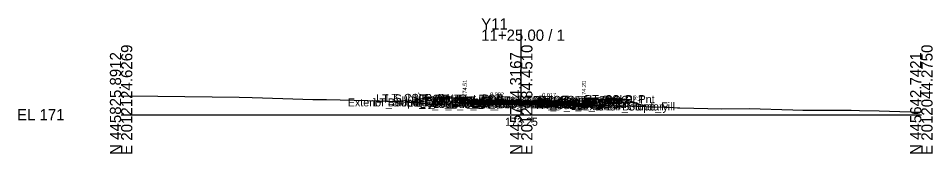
# Model space of a CAD drawing. Extents: x -26 to 203, y -10 to 3517.
# Drawn here: x -25.7 to 202.8, y 2490.3 to 2524 of the extents above; entities that cross this region are included whole.
import ezdxf

# ---------------------------------------------------------------- set-up
doc = ezdxf.new("R2010")
doc.units = 0
for name, color, linetype in [('Default', 7, 'Continuous'), ('Exist Cross Section Cell', 7, 'Continuous'), ('Exist XS Center Line Elevation Label', 7, 'Continuous'), ('Exist XS Ground Line', 7, 'Continuous'), ('Prop CMT Conc Surface', 7, 'Continuous'), ('Prop CMT Concrete Structures', 7, 'Continuous'), ('Prop CMT Pvmt Course 1', 7, 'Continuous'), ('Prop CMT Pvmt Course 1 CG', 7, 'Continuous'), ('Prop CMT Pvmt Course 2', 7, 'Continuous'), ('Prop CMT Pvmt Course 3', 7, 'Continuous'), ('Prop CMT Pvmt Surface', 7, 'Continuous'), ('Prop CMT Slope Grass', 7, 'Continuous'), ('Prop CMT Subgrade Earthwork', 7, 'Continuous'), ('Prop XS Earthwork Shape', 7, 'Continuous'), ('Prop XS Hydro Elevations', 7, 'Continuous'), ('Prop XS SE Text', 7, 'Continuous'), ('Prop XS Side Slope Text', 7, 'Continuous'), ('Scratch_Level_0', 7, 'Continuous')]:
    doc.layers.add(name, color=color, linetype=linetype)

msp = doc.modelspace()

# ---------------------------------------------------------------- linework, layer by layer
at = {"layer": 'Exist Cross Section Cell'}
for p, q in [((100, 2500), (100, 2521.22)), ((0, 2500), (100, 2500)), ((100, 2500), (200, 2500))]:
    msp.add_line(p, q, dxfattribs=at)
at = {"layer": 'Exist XS Ground Line'}
msp.add_lwpolyline([(0, 2504.75), (9.22, 2504.59), (29.53, 2504.38), (32.75, 2504.31), (40.45, 2504.01), (47.93, 2503.83), (51.37, 2503.78), (61.68, 2503.52), (69.29, 2503.3), (73.96, 2502.98), (87.43, 2502.16), (88.96, 2502.1), (91.29, 2502.17), (98.51, 2502.22), (100, 2502.25), (100.43, 2502.25), (108.03, 2502.02), (112.71, 2501.73), (113.1, 2501.82), (113.46, 2502.05), (116.73, 2502.12), (123.62, 2502.21), (128.97, 2502.16), (138.03, 2501.79), (139.02, 2501.76), (139.66, 2501.73), (150.15, 2501.44), (156.98, 2501.55), (167.86, 2501.2), (170.38, 2501.18), (176.95, 2501.13), (182.43, 2501.12), (184.57, 2501.06), (189.45, 2500.96), (194.64, 2500.83), (200, 2500.68)], dxfattribs=at)
at = {"layer": 'Prop CMT Conc Surface'}
for points in [[(85.89, 2503.51), (85.89, 2504.01), (85.39, 2504.01)], [(87.89, 2503.59), (85.89, 2503.51)], [(113.69, 2503.32), (115.69, 2503.2)], [(115.69, 2503.2), (115.69, 2503.7), (116.19, 2503.7)]]:
    msp.add_lwpolyline(points, dxfattribs=at)
at = {"layer": 'Prop CMT Concrete Structures'}
for points in [[(87.89, 2503.59), (85.89, 2503.51), (85.89, 2504.01), (85.39, 2504.01)], [(85.39, 2504.01), (85.39, 2503.01), (87.89, 2503)], [(87.89, 2503), (87.89, 2503.59)], [(113.69, 2503.32), (115.69, 2503.2), (115.69, 2503.7), (116.19, 2503.7)], [(116.19, 2503.7), (116.19, 2502.69), (113.69, 2502.73)], [(113.69, 2502.73), (113.69, 2503.32)]]:
    msp.add_lwpolyline(points, dxfattribs=at)
at = {"layer": 'Prop CMT Pvmt Course 1'}
for points in [[(100, 2503.55), (87.89, 2503.59)], [(87.89, 2503.59), (87.89, 2503.34)], [(87.89, 2503.34), (100, 2503.3)], [(100, 2503.3), (100, 2503.55)], [(100, 2503.55), (113.69, 2503.32)], [(100, 2503.3), (100, 2503.55)], [(113.69, 2503.07), (100, 2503.3)], [(113.69, 2503.32), (113.69, 2503.07)]]:
    msp.add_lwpolyline(points, dxfattribs=at)
msp.add_lwpolyline([(100, 2503.3), (100, 2503.43), (100, 2503.43), (100, 2503.3)], close=True, dxfattribs=at)
msp.add_lwpolyline([(100, 2503.3), (100, 2503.43), (100, 2503.43), (100, 2503.3)], close=True, dxfattribs=at)
at = {"layer": 'Prop CMT Pvmt Course 1 CG'}
for points in [[(87.89, 2503), (84.89, 2503.01), (84.55, 2502.68)], [(84.55, 2502.68), (87.89, 2502.67)], [(87.89, 2502.67), (87.89, 2503)], [(113.69, 2502.73), (116.69, 2502.68), (117.03, 2502.34)], [(113.69, 2502.4), (113.69, 2502.73)], [(117.03, 2502.34), (113.69, 2502.4)]]:
    msp.add_lwpolyline(points, dxfattribs=at)
at = {"layer": 'Prop CMT Pvmt Course 2'}
for points in [[(100, 2503.3), (87.89, 2503.34)], [(87.89, 2503.34), (87.89, 2503)], [(87.89, 2503), (100, 2502.97)], [(100, 2502.97), (100, 2503.3)], [(100, 2502.97), (100, 2503.3)], [(100, 2503.3), (113.69, 2503.07)], [(113.69, 2502.73), (100, 2502.97)], [(113.69, 2503.07), (113.69, 2502.73)]]:
    msp.add_lwpolyline(points, dxfattribs=at)
at = {"layer": 'Prop CMT Pvmt Course 3'}
for points in [[(100, 2502.97), (87.89, 2503)], [(87.89, 2503), (87.89, 2502.67)], [(87.89, 2502.67), (100, 2502.64)], [(100, 2502.64), (100, 2502.97)], [(100, 2502.97), (113.69, 2502.73)], [(100, 2502.64), (100, 2502.97)], [(113.69, 2502.4), (100, 2502.64)], [(113.69, 2502.73), (113.69, 2502.4)]]:
    msp.add_lwpolyline(points, dxfattribs=at)
at = {"layer": 'Prop CMT Pvmt Surface'}
for points in [[(100, 2503.55), (87.89, 2503.59)], [(100, 2503.55), (113.69, 2503.32)]]:
    msp.add_lwpolyline(points, dxfattribs=at)
at = {"layer": 'Prop CMT Slope Grass'}
for points in [[(85.39, 2504.01), (75.89, 2504.2), (72.52, 2503.08)], [(116.19, 2503.7), (125.69, 2503.89), (131.14, 2502.07)]]:
    msp.add_lwpolyline(points, dxfattribs=at)
at = {"layer": 'Prop CMT Subgrade Earthwork'}
for points in [[(87.89, 2502.67), (84.55, 2502.68), (83.18, 2504.05)], [(100, 2502.64), (87.89, 2502.67)], [(100, 2502.64), (113.69, 2502.4)], [(113.69, 2502.4), (117.03, 2502.34), (118.43, 2503.75)]]:
    msp.add_lwpolyline(points, dxfattribs=at)
at = {"layer": 'Prop XS Earthwork Shape'}
msp.add_lwpolyline([(100.43, 2502.25), (108.03, 2502.02), (112.71, 2501.73), (113.1, 2501.82), (113.46, 2502.05), (116.73, 2502.12), (123.62, 2502.21), (128.97, 2502.16), (131.14, 2502.07), (125.69, 2503.89), (118.43, 2503.75), (117.03, 2502.34), (113.69, 2502.4), (100, 2502.64), (87.89, 2502.67), (84.55, 2502.68), (83.18, 2504.05), (75.89, 2504.2), (72.52, 2503.08), (73.96, 2502.98), (87.43, 2502.16), (88.96, 2502.1), (91.29, 2502.17), (98.51, 2502.22), (100, 2502.25)], close=True, dxfattribs=at)

# ---------------------------------------------------------------- texts
at = {"layer": 'Default'}
msp.add_text('-', height=0.0001, dxfattribs=at).set_placement((0, 2500))
at = {"layer": 'Exist Cross Section Cell'}
for s, p in [('Y11', (90, 2521.22)), ('11+25.00 / 1', (90, 2518.42)), ('EL 171', (-26, 2498.6))]:
    msp.add_text(s, height=2.8, dxfattribs=at).set_placement(p)
for s, p in [('E 2012124.6269', (2.8, 2490)), ('E 2012084.4510', (102.8, 2490)), ('E 2012044.2750', (202.8, 2490)), ('N 445825.8912', (0, 2490)), ('N 445734.3167', (100, 2490)), ('N 445642.7421', (200, 2490))]:
    msp.add_text(s, height=2.8, rotation=90, dxfattribs=at).set_placement(p)
at = {"layer": 'Exist XS Center Line Elevation Label'}
msp.add_text('173.25', height=2, dxfattribs=at).set_placement((95.98, 2497.25))
at = {"layer": 'Prop XS Hydro Elevations'}
for s, p in [('174.51', (86.39, 2504.51)), ('174.20', (116.19, 2504.2))]:
    msp.add_text(s, height=1, rotation=90, dxfattribs=at).set_placement(p)
at = {"layer": 'Prop XS SE Text'}
for s, rotation, p in [('0.002', 359.8568, (92.23, 2504.57)), ('0.017', 358.9974, (105.23, 2504.46))]:
    msp.add_text(s, height=1, rotation=rotation, dxfattribs=at).set_placement(p)
at = {"layer": 'Prop XS Side Slope Text'}
for rotation, p in [(18.4332, (73.21, 2504.1)), (341.5668, (127.9, 2503.94))]:
    msp.add_text('3:1', height=1, rotation=rotation, dxfattribs=at).set_placement(p)
at = {"layer": 'Scratch_Level_0'}
for s, p in [('LT_Sub_Trench_Out_DLT', (63.74, 2503.05)), ('LT_CSLP_Pnt', (66.06, 2503.2)), ('LT_CG_Top_Face', (73.15, 2503.01)), ('LT_CG_Top_BOC', (73.67, 2503.01)), ('RT_Sub_Trench_Out_DLT', (98.95, 2502.75)), ('RT_CG_Top_Face', (102.9, 2502.7)), ('RT_CG_Top_BOC', (104.42, 2502.7)), ('RT_CSLP_Pnt', (115.81, 2502.89)), ('Exterior Boundary', (56.66, 2502.08)), ('LT_Slope_Fill', (63.04, 2502.08)), ('LT_CG1_Shelf_Out', (71.44, 2502.01)), ('LT_CG_Bot_BOC', (73.7, 2502.01)), ('LT_CG_Top_Gut', (74.12, 2502.51)), ('LT_Sub_OEOP', (74.66, 2501.68)), ('LT_CG_Bot_IE', (77.8, 2502)), ('LT_Sub_OEOT', (77.97, 2501.67)), ('LT_PV2_OEOT', (78.06, 2502.34)), ('LT_PV3_OEOT', (78.06, 2502)), ('LT_PV1_OEOT', (78.63, 2502.59)), ('RT_Sub_OEEOP', (89.17, 2501.64)), ('LT_Sub_OEEOP', (89.21, 2501.64)), ('RT_PV2_OEEOP', (89.26, 2502.3)), ('RT_PV3_OEEOP', (89.26, 2501.97)), ('LT_PV2_OEEOP', (89.31, 2502.3)), ('LT_PV3_OEEOP', (89.31, 2501.97)), ('RT_PV1_OEEOP', (89.83, 2502.43)), ('LT_PV1_OEEOP', (89.87, 2502.43)), ('RT_PV2_IEEOP', (89.91, 2502.3)), ('LT_PV2_IEEOP', (89.95, 2502.3)), ('RT_PV1_IEEOP', (90.47, 2502.43)), ('LT_PV1_IEEOP', (90.52, 2502.43)), ('PV2_PGL', (93.91, 2502.3)), ('PV1_PGL', (94.47, 2502.55)), ('RT_CG1_Shelf_Out', (103.19, 2501.68)), ('RT_CG_Bot_IE', (103.55, 2501.73)), ('RT_Sub_OEOT', (103.72, 2501.4)), ('RT_PV2_OEOT', (103.81, 2502.07)), ('RT_PV3_OEOT', (103.81, 2501.73)), ('RT_CG_Top_Gut', (103.88, 2502.2)), ('RT_PV1_OEOT', (104.38, 2502.32)), ('RT_CG_Bot_BOC', (104.46, 2501.69)), ('RT_Sub_OEOP', (107.09, 2501.34)), ('Exterior Boundary', (115.28, 2501.07)), ('RT_Slope_Fill', (121.61, 2501.07))]:
    msp.add_text(s, height=2, dxfattribs=at).set_placement(p)

doc.saveas('drawing.dxf')
